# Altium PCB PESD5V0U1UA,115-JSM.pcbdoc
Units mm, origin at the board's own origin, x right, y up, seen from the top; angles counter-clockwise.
Board outline 15.81 x 14.06 mm, 2 copper layers (Top Layer, Bottom Layer), stack 0 mm thick; 1 components, 0 nets, 2 pads, 0 vias.
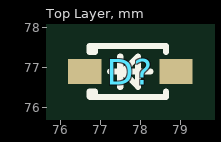
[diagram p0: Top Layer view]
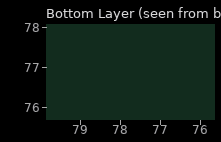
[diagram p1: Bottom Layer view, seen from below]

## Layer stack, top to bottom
Top Layer: signal copper (thickness not stored)
Bottom Layer: signal copper (thickness not stored)

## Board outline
85.66,69.85 69.85,69.85 69.85,83.91 85.66,83.91

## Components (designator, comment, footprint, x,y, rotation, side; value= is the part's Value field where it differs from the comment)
D? "PESD5V0U1UA,115-JSM" SOD-323_L1.7-W1.3-LS2.6-RD-1 77.755,76.91 r0 top

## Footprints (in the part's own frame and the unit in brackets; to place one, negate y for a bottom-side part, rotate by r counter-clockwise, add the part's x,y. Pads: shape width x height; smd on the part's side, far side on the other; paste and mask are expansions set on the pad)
SOD-323_L1.7-W1.3-LS2.6-RD-1 [mm]
  rect 0.83x0.63 smd paste+0 mask+0.05: 1(-1.14,0) 2(1.14,0)
  silkscreen extent -1.02,-0.64 0.89,0.64

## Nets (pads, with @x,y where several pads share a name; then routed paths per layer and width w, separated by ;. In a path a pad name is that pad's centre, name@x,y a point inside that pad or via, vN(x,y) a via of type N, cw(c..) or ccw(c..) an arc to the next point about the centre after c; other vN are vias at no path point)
pads on no net: D?.1 D?.2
